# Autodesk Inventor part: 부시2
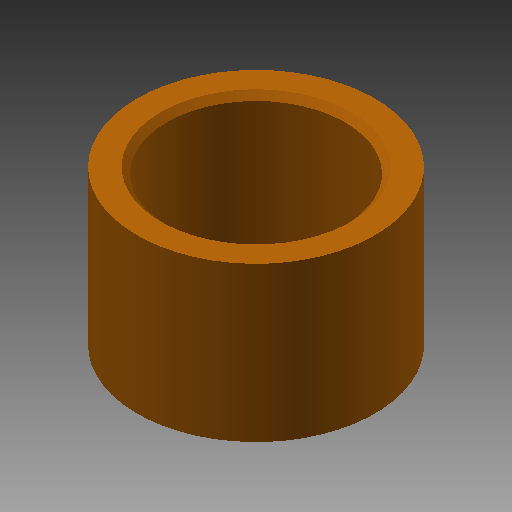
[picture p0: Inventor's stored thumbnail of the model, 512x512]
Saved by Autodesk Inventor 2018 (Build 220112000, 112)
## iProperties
Created: 2016-08
Part Number: 부시2
Material: 강철, 탄소
Document SubType Name: Modeling
Designer: mduedu
Density: 7.87 g/cm^3
Appearance: 주황색
Author: mduedu
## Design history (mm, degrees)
sketch "스케치1"
  geometry: C1 r 7.5 at (0, 0); C2 r 10 at (0, 0); 1 further point
  constraints: 2 centre point, 2 coincident
  dimensions: "d0" = 15 diameter of C1; "d1" = 20 diameter of C2
extrude "돌출1" new body sketch "스케치1" stored distance "d2" = 13; taper "d3" = 0 deg
chamfer "모따기1" distance "d4" = 0.5; stored, may be unused: second distance "d5" = 2, angle "d6" = 45 deg
node "솔리드1"
